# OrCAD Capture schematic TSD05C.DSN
size A; title: TSDxxC Bidrectional TVS Diodes in SOD-323 Package; rev: 1.0; note: Datasheet: SLVSH42
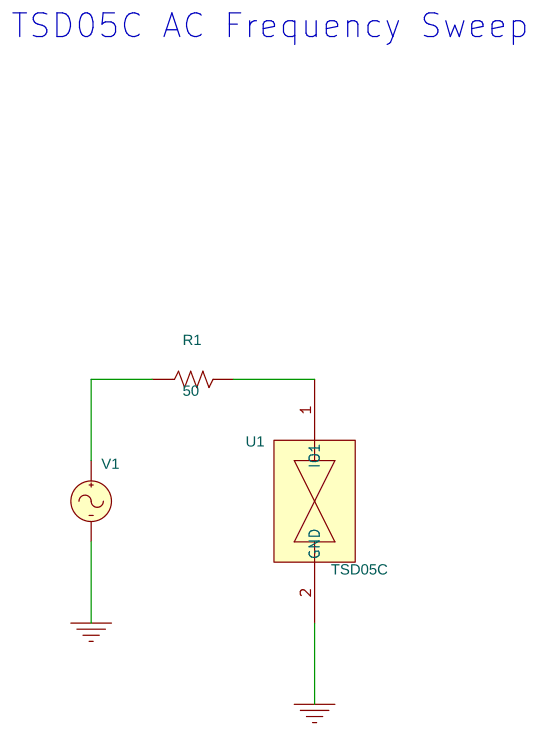
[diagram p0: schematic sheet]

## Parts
R1  50  [AXRC05]
U1  TSD05C
V1  VAC

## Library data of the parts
R1 = R
U1 = TSD05C
V1 = VAC

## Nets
0: U1.2(GND) V1.2(-)
N00400: R1.1 V1.1(+)
N00407: R1.2 U1.1(IO1)

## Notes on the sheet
- TSD05C AC Frequency Sweep
